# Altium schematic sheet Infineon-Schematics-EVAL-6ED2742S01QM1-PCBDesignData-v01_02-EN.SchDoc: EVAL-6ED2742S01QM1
size A3; ApprovedBy: IFCX; Author: Liang Guozhu; CompanyName: Infineon Technologies Xi’an Co., Ltd; Engineer: <Rel.>; Organization: IFCX IPC ISD SYS; Address1: IFCX IPC ISD SYS; Address2: 3rd Floor, No.16, District C, ChuangYe Park,; Address3: No.69 JinYe Road,High-tech Zone, Xi'an, Shaanxi,710077 P.R.C; Address4: China; DocumentNumber: 1; Revision: V1.1; SheetNumber: 1; SheetTotal: 1; Release: No; PageSetup: Record=PageOptions¦CenterHorizontal=True¦CenterVertical=True¦PrintScale=1.01¦XCorrection=1.00¦YCorrection=1.00¦PrintKind=0¦BorderSize=5000000¦LeftOffset=0¦BottomOffset=0¦Orientation=2¦PaperLength=1000¦PaperWidth=1000¦Scale=100¦PaperSource=7¦PrintQuality=-4¦MediaType=1¦DitherType=10¦PaperKind=A3¦PrintScaleMode=1; Doc_ConfidentialStatus: <Doc_ConfidentialStatus>; Doc_Preliminary: <Doc_Preliminary>
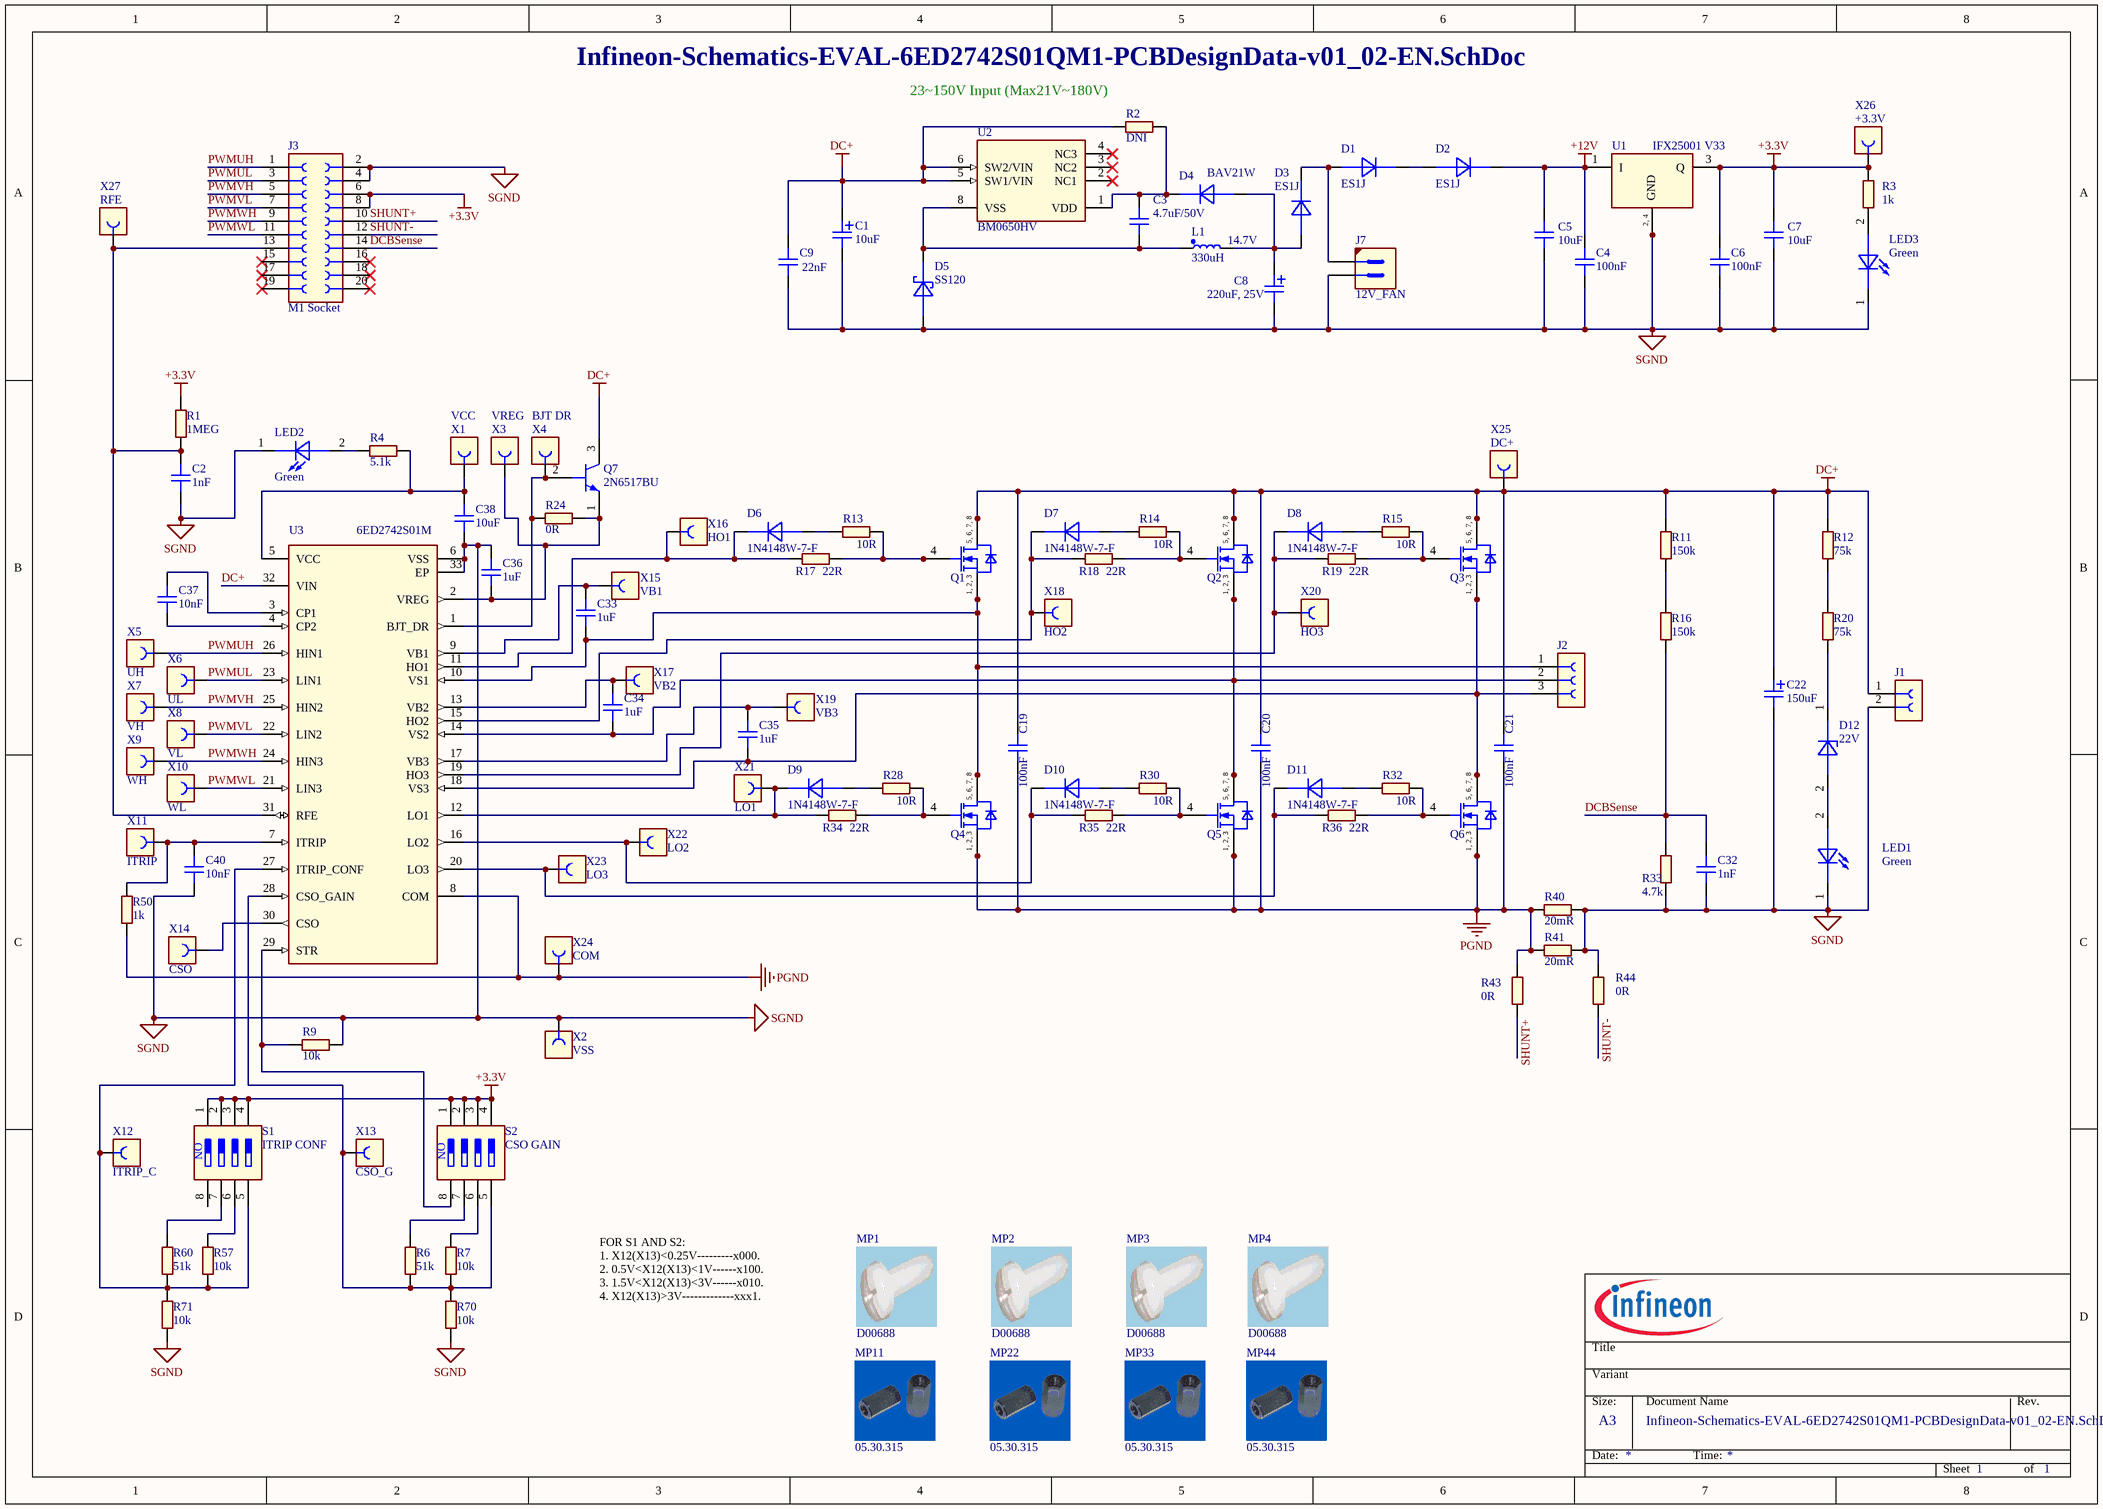
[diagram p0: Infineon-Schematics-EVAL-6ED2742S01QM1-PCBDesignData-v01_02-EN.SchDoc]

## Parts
C1  10uF  [CAPPRD500W60D1000H2150B]
C2  1nF  [CAPC1608X90N]
C3  4.7uF/50V  [CAPC2013X135N]
C4  100nF  [CAPC2013X94N]
C5  10uF  [CAPC1608X90N]
C6  100nF  [CAPC2013X94N]
C7  10uF  [CAPC1608X90N]
C8  220uF, 25V  [CAPPRD350W60D800H1300B]
C9  22nF  [CAPC2013X135N]
C19  100nF  [CAPC3216X180N-2]
C20  100nF  [CAPC3216X180N-2]
C21  100nF  [CAPC3216X180N-2]
C22  150uF  [CAPPRD750W80D1800H2650B]
C32  1nF  [CAPC2013X88N]
C33  1uF  [CAPC1608X90N]
C34  1uF  [CAPC1608X90N]
C35  1uF  [CAPC1608X90N]
C36  1uF  [CAPC1608X90N]
C37  10nF  [CAPC1608X90N]
C38  10uF  [CAPC2013X95N]
C40  10nF  [CAPC1608X90N]
D1  ES1J  [DIOM5027X244N-1]
D2  ES1J  [DIOM5027X244N-1]
D3  ES1J  [DIOM5027X244N-1]
D4  BAV21W  [SOD3715X145N]
D5  SS120  [DIOM5127X229N]
D6  1N4148W-7-F  [SOD3715X145N]
D7  1N4148W-7-F  [SOD3715X145N]
D8  1N4148W-7-F  [SOD3715X145N]
D9  1N4148W-7-F  [SOD3715X145N]
D10  1N4148W-7-F  [SOD3715X145N]
D11  1N4148W-7-F  [SOD3715X145N]
D12  22V  [DIOMELF3516N-1]
J1  691216510002S  [CON-TER-THT-691216510002S]  (value not drawn)
J2  691216510003S  [CON-TER-THT-691216510003S]  (value not drawn)
J3  M1 Socket  [CON-F-THT-613020243121]
J7  12V_FAN  [CON-M-THT-61300211121]
L1  330uH  [INDRD500W65D950H1350B]
LED1  Green  [LEDSC160X80X80-2N-1]
LED2  Green  [LEDSC160X80X80-2N-1]
LED3  Green  [LEDSC160X80X80-2N-1]
MP1  D00688  [SCREW_M3X10_D00688]
MP2  D00688  [SCREW_M3X10_D00688]
MP3  D00688  [SCREW_M3X10_D00688]
MP4  D00688  [SCREW_M3X10_D00688]
MP11  05.30.315  [HEX-STANDOFF_M3X15_0530315]
MP22  05.30.315  [HEX-STANDOFF_M3X15_0530315]
MP33  05.30.315  [HEX-STANDOFF_M3X15_0530315]
MP44  05.30.315  [HEX-STANDOFF_M3X15_0530315]
Q1  igfet_n_ch_enh_dio_1s2s3s4g5d6d7d8d_8p  [IFX-PG-TSON-8-3]  (value not drawn)
Q2  igfet_n_ch_enh_dio_1s2s3s4g5d6d7d8d_8p  [IFX-PG-TSON-8-3]  (value not drawn)
Q3  igfet_n_ch_enh_dio_1s2s3s4g5d6d7d8d_8p  [IFX-PG-TSON-8-3]  (value not drawn)
Q4  igfet_n_ch_enh_dio_1s2s3s4g5d6d7d8d_8p  [IFX-PG-TSON-8-3]  (value not drawn)
Q5  igfet_n_ch_enh_dio_1s2s3s4g5d6d7d8d_8p  [IFX-PG-TSON-8-3]  (value not drawn)
Q6  igfet_n_ch_enh_dio_1s2s3s4g5d6d7d8d_8p  [IFX-PG-TSON-8-3]  (value not drawn)
Q7  2N6517BU  [TO-92-THT-2N6517BU]
R1  1MEG  [RESC1609X50N]
R2  DNI  [RESC3216X60N]
R3  1k  [RESC2113X50N]
R4  5.1k  [RESC1609X50N]
R6  51k  [RESC1609X50N]
R7  10k  [RESC1608X55N-1]
R9  10k  [RESC1608X55N-1]
R11  150k  [RESC2113X50N]
R12  75k  [RESC2113X50N]
R13  10R  [RESC2113X50N]
R14  10R  [RESC2113X50N]
R15  10R  [RESC2113X50N]
R16  150k  [RESC2113X50N]
R17  22R  [RESC2113X50N]
R18  22R  [RESC2113X50N]
R19  22R  [RESC2113X50N]
R20  75k  [RESC2113X50N]
R24  0R  [RESC1608X55N-1]
R28  10R  [RESC2113X50N]
R30  10R  [RESC2113X50N]
R32  10R  [RESC2113X50N]
R33  4.7k  [RESC2013X60N-1]
R34  22R  [RESC2113X50N]
R35  22R  [RESC2113X50N]
R36  22R  [RESC2113X50N]
R40  20mR  [RESC6432X89N-1]
R41  20mR  [RESC6432X89N-1]
R43  0R  [RESC2113X50N]
R44  0R  [RESC2113X50N]
R50  1k  [RESC1608X55N-1]
R57  10k  [RESC1608X55N-1]
R60  51k  [RESC1609X50N]
R70  10k  [RESC1608X55N-1]
R71  10k  [RESC1608X55N-1]
S1  ITRIP CONF  [SW-DIP-SMD-A6H-4102]
S2  CSO GAIN  [SW-DIP-SMD-A6H-4102]
U1  IFX25001 V33  [SOT230P700X170-4N-1]
U2  BM0650HV  [SOIC127P600X175-7_8N]
U3  6ED2742S01M  [QFN50P500X500X90-33N-V]
X1  VCC  [TPCW140D210H530]
X2  VSS  [TPCW140D210H530]
X3  VREG  [TPCW140D210H530]
X4  BJT DR  [TPCW140D210H530]
X5  UH  [TPCW140D210H530]
X6  UL  [TPCW140D210H530]
X7  VH  [TPCW140D210H530]
X8  VL  [TPCW140D210H530]
X9  WH  [TPCW140D210H530]
X10  WL  [TPCW140D210H530]
X11  ITRIP  [TPCW140D210H530]
X12  ITRIP_C  [TPCW140D210H530]
X13  CSO_G  [TPCW140D210H530]
X14  CSO  [TPCW140D210H530]
X15  VB1  [TPCW140D210H530]
X16  HO1  [TPCW140D210H530]
X17  VB2  [TPCW140D210H530]
X18  HO2  [TPCW140D210H530]
X19  VB3  [TPCW140D210H530]
X20  HO3  [TPCW140D210H530]
X21  LO1  [TPCW140D210H530]
X22  LO2  [TPCW140D210H530]
X23  LO3  [TPCW140D210H530]
X24  COM  [TPCW140D210H530]
X25  DC+  [TPCW140D210H530]
X26  +3.3V  [TPCW140D210H530]
X27  RFE  [TPCW140D210H530]

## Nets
+3.3V: C6.2 C7.1 J3.6 J3.8 R1.2 R3.2 S1.1 S1.2 S1.3 S1.4 S2.1 S2.2 S2.3 S2.4 U1.3(Q) X26.1
+12V: C4.2 C5.1 D2.1(Cathode) U1.1(I)
DC+: C1.1 C9.2 C19.2 C20.2 C21.2 C22.1 J1.1 Q1.5(DRAIN) Q1.6(DRAIN) Q1.7(DRAIN) Q1.8(DRAIN) Q2.5(DRAIN) Q2.6(DRAIN) Q2.7(DRAIN) Q2.8(DRAIN) Q3.5(DRAIN) Q3.6(DRAIN) Q3.7(DRAIN) Q3.8(DRAIN) Q7.3(COLLECTOR) R2.1 R11.2 R12.2 U2.5(SW1/VIN) U2.6(SW2/VIN) U3.32(VIN) X25.1
PGND: C19.1 C20.1 C21.1 Q4.1(SOURCE) Q4.2(SOURCE) Q4.3(SOURCE) Q5.1(SOURCE) Q5.2(SOURCE) Q5.3(SOURCE) Q6.1(SOURCE) Q6.2(SOURCE) Q6.3(SOURCE) R40.1 R41.1 R43.1 R50.1 U3.8(COM) X24.1
SGND: C1.2 C2.1 C4.1 C5.2 C6.1 C7.2 C8.2 C9.1 C22.2 C32.1 C36.2 C38.2 C40.1 D5.2(Anode) J1.2 J3.2 J3.4 J7.2 LED1.1(Cathode) LED2.1(Cathode) LED3.1(Cathode) R9.2 R33.2 R40.2 R41.2 R44.2 R70.1 R71.1 U1.2(GND) U1.4(GND) U3.6(VSS) U3.33(EP) X2.1
DCBSense: C32.2 J3.14 R16.1 R33.1
PWMUH: J3.1 U3.26(HIN1) X5.1
PWMUL: J3.3 U3.23(LIN1) X6.1
PWMVH: J3.5 U3.25(HIN2) X7.1
PWMVL: J3.7 U3.22(LIN2) X8.1
PWMWH: J3.9 U3.24(HIN3) X9.1
PWMWL: J3.11 U3.21(LIN3) X10.1
SHUNT+: J3.10 R43.2
SHUNT-: J3.12 R44.1
NetC2_2: C2.2 J3.13 R1.1 U3.31(RFE) X27.1
NetC3_1: C3.1 D5.1(Cathode) L1.1 U2.8(VSS)
NetC3_2: C3.2 D4.1(Cathode) R2.2 U2.1(VDD)
NetC8_1: C8.1 D3.2(Anode) D4.2(Anode) L1.2
NetC33_1: C33.1 J2.1 Q1.1(SOURCE) Q1.2(SOURCE) Q1.3(SOURCE) Q4.5(DRAIN) Q4.6(DRAIN) Q4.7(DRAIN) Q4.8(DRAIN) U3.10(VS1)
NetC33_2: C33.2 U3.9(VB1) X15.1
NetC34_1: C34.1 J2.2 Q2.1(SOURCE) Q2.2(SOURCE) Q2.3(SOURCE) Q5.5(DRAIN) Q5.6(DRAIN) Q5.7(DRAIN) Q5.8(DRAIN) U3.14(VS2)
NetC34_2: C34.2 U3.13(VB2) X17.1
NetC35_1: C35.1 J2.3 Q3.1(SOURCE) Q3.2(SOURCE) Q3.3(SOURCE) Q6.5(DRAIN) Q6.6(DRAIN) Q6.7(DRAIN) Q6.8(DRAIN) U3.18(VS3)
NetC35_2: C35.2 U3.17(VB3) X19.1
NetC36_1: C36.1 Q7.1(EMITTER) R24.2 U3.2(VREG) X3.1
NetC37_1: C37.1 U3.4(CP2)
NetC37_2: C37.2 U3.3(CP1)
NetC38_1: C38.1 R4.2 U3.5(VCC) X1.1
NetC40_2: C40.2 R50.2 U3.7(ITRIP) X11.1
NetD1_1: D1.1(Cathode) D2.2(Anode)
NetD1_2: D1.2(Anode) D3.1(Cathode) J7.1
NetD6_1: D6.1(Cathode) R17.1 U3.11(HO1) X16.1
NetD6_2: D6.2(Anode) R13.1
NetD7_1: D7.1(Cathode) R18.1 U3.15(HO2) X18.1
NetD7_2: D7.2(Anode) R14.1
NetD8_1: D8.1(Cathode) R19.1 U3.19(HO3) X20.1
NetD8_2: D8.2(Anode) R15.1
NetD9_1: D9.1(Cathode) R34.1 U3.12(LO1) X21.1
NetD9_2: D9.2(Anode) R28.1
NetD10_1: D10.1(Cathode) R35.1 U3.16(LO2) X22.1
NetD10_2: D10.2(Anode) R30.1
NetD11_1: D11.1(Cathode) R36.1 U3.20(LO3) X23.1
NetD11_2: D11.2(Anode) R32.1
NetD12_1: D12.1(CATHODE) R20.1
NetD12_2: D12.2(ANODE) LED1.2(Anode)
NetLED2_2: LED2.2(Anode) R4.1
NetLED3_2: LED3.2(Anode) R3.1
NetQ1_4: Q1.4(GATE) R13.2 R17.2
NetQ2_4: Q2.4(GATE) R14.2 R18.2
NetQ3_4: Q3.4(GATE) R15.2 R19.2
NetQ4_4: Q4.4(GATE) R28.2 R34.2
NetQ5_4: Q5.4(GATE) R30.2 R35.2
NetQ6_4: Q6.4(GATE) R32.2 R36.2
NetQ7_2: Q7.2(BASE) R24.1 U3.1(BJT_DR) X4.1
NetR6_1: R6.1 R7.1 R70.2 S2.5 U3.28(CSO_GAIN) X13.1
NetR6_2: R6.2 S2.7
NetR7_2: R7.2 S2.6
NetR9_1: R9.1 S2.8 U3.29(STR)
NetR11_1: R11.1 R16.2
NetR12_1: R12.1 R20.2
NetR57_1: R57.1 R60.1 R71.2 S1.5 U3.27(ITRIP_CONF) X12.1
NetR57_2: R57.2 S1.6
NetR60_2: R60.2 S1.7
NetU3_30: U3.30(CSO) X14.1

Not connected (* = marked no-connect by the designer): J3 15* 16* 17* 18* 19* 20*; S1 8; U2 2(NC1)* 3(NC2)* 4(NC3)*

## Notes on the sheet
- (near R2) 23
  50V Input (Max21V
  80V)
- (near L1) 14.7V
- FOR S1 AND S2:
  1. X12(X13)<0.25V---------x000.
  2. 0.5V<X12(X13)<1V------x100.
  3. 1.5V<X12(X13)<3V------x010.
  4. X12(X13)>3V-------------xxx1.

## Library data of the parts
C1 = 641748: CAP / ELCO / 10uF / 200V / 20% / Aluminiumelectrolytic / -25¡ãC to 105¡ãC / 5.00mm C X 0.60mm W 10.00mm Dia X 21.50mm H / - / -; Multible Parts: No; Manufacturer: Wurth Elektronik; Manufacturer Order Number: 860241075003; Symbol Type: Capacitor; Single; Polarized; 2 Pins; Pin 1 Positive; Alternate View: Yes; Article Number: 641748; Version Number: V01; Combined Parameters: TC:Aluminiumelectrolytic;Tol.:-20%/+20%;Vdc:200V; QuickPick: 10uF / 200V / 20% / Aluminiumelectrolytic / Radial; Type: Polarized; Style: Single; ComponentStatus: Released; PLMStatus: Active
C2 = 272935: CAP / - / 1nF / 25V / 10% / X7R (EIA) / -55¡ãC to 125¡ãC / 0603(1608) / SMD / -; Multiple Parts: No; Legacy PartNumber: CAP01003594; Manufacturer: MuRata; Manufacturer Order Number: GRM188R71E102KA01; Symbol Type: Capacitor; Single; Standard; 2 Pins; Alternate View: Yes; Article Number: 272935; Version Number: V01; Combined Parameters: TC:X7R (EIA);Tol.:-10%/+10%;Vdc:25V; QuickPick: 1nF / 25V / 10% / X7R (EIA) / CAPC1608X90N; Type: Standard; Style: Single; Package Metric: 1608; Package Imperial: 0603; ComponentStatus: Released; PLMStatus: Obsolete
C3 = 278629: Chip Monolithic Ceramic Capacitor; Multiple Parts: No; Legacy PartNumber: CAP01004770; Manufacturer: MuRata; Manufacturer Order Number: GRM21BR61H475KE51; Symbol Type: Capacitor; Single; Standard; 2 Pins; Alternate View: Yes; Article Number: 278629; Version Number: V01; Value: 4.7uF; Tolerance Neg: 10%; Combined Parameters: TC:X5R (EIA);Tol.:-10%/+10%;Vdc:50V; QuickPick: 4.7uF / 50V / 10% / X5R (EIA) / CAPC2013X135N; Type: Standard; Style: Single; Package Metric: 2012; Package Imperial: 0805; ComponentStatus: Released; PLMStatus: Active; Voltage DC (max): 50V
C4 C6 = 254358: Surface Mount Ceramic Capacitor 0.1uF 25V X7R 10%; Multiple Parts: No; Manufacturer: AVX; Manufacturer Order Number: 08053C104K4Z2A; Symbol Type: Capacitor; Single; Standard; 2 Pins; Alternate View: Yes; Article Number: 254358; Version Number: V00; Combined Parameters: TC:X7R (EIA);Tol.:-10%/+10%;Vdc:25V; QuickPick: 100nF / 25V / 10% / X7R (EIA) / 0805 (2012); Type: Standard; Style: Single; Automotive Qualified: AEC Q200; PLMStatus: Active
C5 C7 = 271780: Chip Monolithic Ceramic Capacitor; Multiple Parts: No; Legacy PartNumber: CAP01003363; Manufacturer: MuRata; Manufacturer Order Number: GRM188R60J106ME84; Symbol Type: Capacitor; Single; Standard; 2 Pins; Alternate View: Yes; Article Number: 271780; Version Number: V01; Tolerance Neg: 20%; Combined Parameters: TC:X5R (EIA);Tol.:-20%/+20%;Vdc:6.3V; QuickPick: 10uF / 6.3V / 20% / X5R (EIA) / CAPC1608X90N; Type: Standard; Style: Single; Package Metric: 1608; Package Imperial: 0603; ComponentStatus: Released; PLMStatus: Active; Voltage DC (max): 6.30V
C8 = 636068: CAP / ELCO / 220uF / 25V / 20% / Aluminiumelectrolytic / -40¡ãC to 105¡ãC / 3.50mm C X 0.60mm W 8.00mm Dia X 13.00mm H / - / -; Multible Parts: No; Manufacturer: Wurth Elektronik; Manufacturer Order Number: 860020474012; Symbol Type: Capacitor; Single; Polarized; 2 Pins; Pin 1 Positive; Alternate View: Yes; Article Number: 636068; Version Number: V01; Combined Parameters: TC:Aluminiumelectrolytic;Tol.:-20%/+20%;Vdc:25V; QuickPick: 220uF / 25V / 20% / Aluminiumelectrolytic / Radial; Type: Polarized; Style: Single; ComponentStatus: Released; PLMStatus: Active
C9 = 279773: CAP / - / 22nF / 250V / 10% / X7R (EIA) / -55¡ãC to 125¡ãC / 0805(2012) / SMD / -; Multiple Parts: No; Legacy PartNumber: CAP01005000; Manufacturer: MuRata; Manufacturer Order Number: GRM21BR72E223KW03; Symbol Type: Capacitor; Single; Standard; 2 Pins; Alternate View: Yes; Article Number: 279773; Version Number: V01; Combined Parameters: TC:X7R (EIA);Tol.:-10%/+10%;Vdc:250V; QuickPick: 22nF / 250V / 10% / X7R (EIA) / CAPC2013X135N; Type: Standard; Style: Single; Package Metric: 2012; Package Imperial: 0805; ComponentStatus: Released; PLMStatus: Not Recommended For New Designs
C19-C21 = 610534: Ceramic Capacitor 0.1uF 250V X7R 10% SMD 1206; Multiple Parts: No; Manufacturer: Samsung; Manufacturer Order Number: CL31B104KEHSNNE; Symbol Type: Capacitor; Single; Standard; 2 Pins; Alternate View: Yes; Article Number: 610534; Version Number: V01; Combined Parameters: TC:X7R (EIA);Tol.:-10%/+10%;Vdc:250V; QuickPick: 100nF / 250V / 10% / X7R (EIA) / 1206; Type: Standard; Style: Single; ComponentStatus: Released; PLMStatus: Active
C22 = 641470: CAP / ELCO / 150uF / 200V / 20% / Aluminiumelectrolytic / -25¡ãC to 105¡ãC / 7.50mm C X 0.80mm W 18.00mm Dia X 26.50mm H / - / -; Multible Parts: No; Manufacturer: Wurth Elektronik; Manufacturer Order Number: 860241081008; Symbol Type: Capacitor; Single; Polarized; 2 Pins; Pin 1 Positive; Alternate View: Yes; Article Number: 641470; Version Number: V01; Combined Parameters: TC:Aluminiumelectrolytic;Tol.:-20%/+20%;Vdc:200V; QuickPick: 150uF / 200V / 20% / Aluminiumelectrolytic / Radial; Type: Polarized; Style: Single; ComponentStatus: Released; PLMStatus: Active
C32 = 251057: Surface Mount Multilayer Ceramic Chip Capacitor; Multiple Parts: No; Legacy PartNumber: CAP00004113; Manufacturer: Kemet; Manufacturer Order Number: C0805C102K5RACTU; Symbol Type: Capacitor; Single; Standard; 2 Pins; Alternate View: Yes; Article Number: 251057; Version Number: V01; Tolerance Neg: 10%; Combined Parameters: TC:X7R (EIA);Tol.:-10%/+10%;Vdc:50V; QuickPick: 1nF / 50V / 10% / X7R (EIA) / 0805; Type: Standard; Style: Single; Package Metric: 2012; Package Imperial: 0805; PLMStatus: Active; Voltage DC (max): 50V
C33-C36 = 272975: CAP / - / 1uF / 25V / 10% / X7R (EIA) / -55¡ãC to 125¡ãC / 0603(1608) / SMD / -; Multiple Parts: No; Legacy PartNumber: CAP01003602; Manufacturer: MuRata; Manufacturer Order Number: GRM188R71E105KA12; Symbol Type: Capacitor; Single; Standard; 2 Pins; Alternate View: Yes; Article Number: 272975; Version Number: V01; Combined Parameters: TC:X7R (EIA);Tol.:-10%/+10%;Vdc:25V; QuickPick: 1uF / 25V / 10% / X7R (EIA) / CAPC1608X90N; Type: Standard; Style: Single; Package Metric: 1608; Package Imperial: 0603; ComponentStatus: Released; PLMStatus: Active
C37 C40 = 272945: CAP / - / 10nF / 25V / 5% / X7R (EIA) / -55¡ãC to 125¡ãC / 0603(1608) / SMD / -; Multiple Parts: No; Legacy PartNumber: CAP01003596; Manufacturer: MuRata; Manufacturer Order Number: GRM188R71E103JA01; Symbol Type: Capacitor; Single; Standard; 2 Pins; Alternate View: Yes; Article Number: 272945; Version Number: V01; Combined Parameters: TC:X7R (EIA);Tol.:-5%/+5%;Vdc:25V; QuickPick: 10nF / 25V / 5% / X7R (EIA) / CAPC1608X90N; Type: Standard; Style: Single; Package Metric: 1608; Package Imperial: 0603; ComponentStatus: Released; PLMStatus: Not Recommended For New Designs
C38 = 277107: Chip Monolithic Ceramic Capacitor; Multiple Parts: No; Legacy PartNumber: CAP01004436; Manufacturer: MuRata; Manufacturer Order Number: GRM219R61E106KA12; Symbol Type: Capacitor; Single; Standard; 2 Pins; Alternate View: Yes; Article Number: 277107; Version Number: V01; Tolerance Neg: 10%; Combined Parameters: TC:X5R (EIA);Tol.:-10%/+10%;Vdc:25V; QuickPick: 10uF / 25V / 10% / X5R (EIA) / CAPC2013X95N; Type: Standard; Style: Single; Package Metric: 2012; Package Imperial: 0805; PLMStatus: Active; Voltage DC (max): 25V
D1-D3 = 394773: 1.0A Ultra Fast Recovery Rectifier; Legacy PartNumber: DIO01300264; Manufacturer: ON Semiconductor; Symbol Type: Standard Diode Symbol, 2 Leads, 1 Cathode, 2 Anode; Article Number: 394773; Version Number: V01; Combined Parameters: Vf:1.7V;If:1A;Ur:600V;Ir:5uA;Pmax:1.47W; QuickPick: Standard Diode / SMA (DO-214AC); Type: Standard Diode; Style: Single; Automotive Qualified: No; ComponentStatus: Released; PLMStatus: Active; Second Source allowed: Yes; Voltage DC (max): na
D4 = 394723: Surface Mount Fast Switching Diode; Legacy PartNumber: DIO01300257; Manufacturer: Diodes Incorporated; Manufacturer Order Number: BAV19W-7-F; Symbol Type: Standard Diode Symbol, 2 Leads, 1 Cathode, 2 Anode; Article Number: 394723; Version Number: V01; Value: BAV19W-7-F; Combined Parameters: Vf:1.5V;If:400mA;Ur:120V;Ir:100uA;Pmax:250mW; QuickPick: Standard Diode / SOD-123; Type: Standard Diode; Style: Single; Automotive Qualified: AEC Q101; ComponentStatus: Released; PLMStatus: Active; Second Source allowed: Yes; Voltage DC (max): na
D5 = 394491: Surface Mount Schottky Barrier Rectifier, 20V; Legacy PartNumber: DIO01300226; Manufacturer: Vishay; Manufacturer Order Number: SS12HE3_B/H; Symbol Type: Standard Schottky Diode Symbol, 1 Cathode, 2 Anode; Article Number: 394491; Version Number: V01; Value: SS12HE3_B/H; Combined Parameters: Vf:500mV;If:1A;Ur:20V;Ir:200uA;Pmax:-; QuickPick: Schottky Diode / DO-214AC (SMA); Type: Schottky Diode; Style: Single; Automotive Qualified: AEC Q101; PLMStatus: Active; Second Source allowed: Yes; Voltage DC (max): na
D6-D11 = 394268: Surface Mount Fast Switching Diode; Legacy PartNumber: DIO01300202; Manufacturer: Diodes Incorporated; Symbol Type: Standard Diode Symbol, 2 Leads, 1 Cathode, 2 Anode; Article Number: 394268; Version Number: V01; Combined Parameters: Vf:1.25V;If:300mA;Ur:100V;Ir:1uA;Pmax:400mW; QuickPick: Standard Diode / SOD123; Type: Standard Diode; Style: Single; Automotive Qualified: No; ComponentStatus: Released; PLMStatus: Active; Second Source allowed: Yes; Voltage DC (max): na
D12 = 394392: Zener Diode, 5% 22V; Legacy PartNumber: DIO01300216; Manufacturer: Solid State Devices Inc.; Manufacturer Order Number: SZ25B22SM; Symbol Type: Standard Zener Diode, 1 Cathode, 2 Anode; Article Number: 394392; Version Number: V01; Combined Parameters: Vf:-;If:-;Ur:17V;Ir:100nA;Pmax:-; QuickPick: Zener Diode / SMD; Style: Single; Automotive Qualified: No; ComponentStatus: Released; PLMStatus: Active; Second Source allowed: Yes; Voltage DC (max): na
J1 = 629821: Horizontal Cable Entry With Rising Cage Clamp - WR-TBL, 2 Pins; Manufacturer: Wurth Elektronik; Article Number: 629821; Version Number: V01; Legacy DeviceID: WE_691216510002S; Combined Parameters: Board-to-Cable Socket (female);2x1;Mounting:Onboard;Orient:0¡ã (vertical);Shielded:No; QuickPick: 0¡ã (vertical) / Board-to-Cable; Style: Terminal Block; Automotive Qualified: No; ComponentStatus: Released; PLMStatus: Active; Second Source allowed: Yes; Voltage DC (max): na
J2 = 618457: Horizontal Cable Entry With Rising Cage Clamp - WR-TBL, 3Pins; Manufacturer: Wurth Elektronik; Article Number: 618457; Version Number: V01; Legacy DeviceID: WE_691216510003S; Combined Parameters: Board-to-Cable Socket (female);3x1;Mounting:THT;Orient:0¡ã (vertical);Shielded:No; QuickPick: 0¡ã (vertical) / Board-to-Cable; Style: Terminal Block; Automotive Qualified: No; ComponentStatus: Released; PLMStatus: Active; Second Source allowed: Yes; Voltage DC (max): na
J3 = 618241: WR-PHD 2.54 mm Angled Dual Socket Header; Manufacturer: Wurth Elektronik; Manufacturer Order Number: 613020243121; Symbol type: Socket 10X2 pins; Article Number: 618241; Version Number: V01; Legacy DeviceID: WE_613020243121; Value: 613020243121; Combined Parameters: Board-to-Board Socket (female);10x2;Mounting:THT;Orient:90¡ã (right angle);Shielded:No; QuickPick: 90¡ã (right angle) / Board-to-Board; Automotive Qualified: No; ComponentStatus: Released; PLMStatus: Active; Second Source allowed: Yes; Voltage DC (max): na
J7 = 386760: Header, 2.54mm Pitch, 2 pin, Vertical, Single Row; Legacy PartNumber: CON01500943; Manufacturer: Wurth Elektronik; Manufacturer Order Number: 61300211121; Article Number: 386760; Version Number: V01; Legacy DeviceID: WE_61300211121; Value: 61300211121; Combined Parameters: Board-to-Board Header (male);2x1;Mounting:THT;Orient:0Â° (vertical);Shielded:No; QuickPick: 0Â° (vertical) / Board-to-Board; Style: Strip; Automotive Qualified: No; PLMStatus: Active; Second Source allowed: Yes; Voltage DC (max): na
L1 = 641478: IND / STD / 330uH / 1.1A / 10% / -40¡ãC to 125¡ãC / 470mR / Radial / Inductor,Radial;5.00mm C X 0.65mm W 9.50mm Dia X 13.50mm H / - / -; Multiple Parts: No; Manufacturer: Wurth Elektronik; Manufacturer Order Number: 7447452331; Symbol Type: Inductor; Single; Standard; Polarized; 2 Pins; Alternate View: Yes; Article Number: 641478; Version Number: V01; Combined Parameters: Tol.:-10%/+10%;Rdc:470mR;Idc:1.1A;Fres:2.4MHz; QuickPick: 330uH / Standard / Radial; Type: Standard; Style: Single; ComponentStatus: Released; PLMStatus: Active; Voltage DC (max): na
LED1-LED3 = 625451: WL-SMCW SMT Mono-color Chip LED Waterclear, Green, 515nm; Manufacturer: Wurth Elektronik; Manufacturer Order Number: 150060GS75000; Symbol Type: Standard LED Symbol, 1 Cathode, 2 Anode; Article Number: 625451; Version Number: V01; Combined Parameters: Vf:3.5V;If:30mA;Ur:5V;Ir:10uA;Pmax:105mW; QuickPick: LED / 1608 (0603); Style: Single; Automotive Qualified: No; ComponentStatus: Released; PLMStatus: Active; Second Source allowed: Yes; Voltage DC (max): na
MP1-MP4 = 416878: M3 X 10mm Pan Head,Cross Head Metric Screw, 5.6mm X 2.4mm Head, Nylon 6,6; Legacy PartNumber: MEC10000028; Manufacturer: Duratool; Symbol Type: Pan,Cross Head Metric Screw , M3/M4/M5/M6 types; Article Number: 416878; Version Number: V01; Legacy DeviceID: MEC_D00688; Combined Parameters: - - -x- -; Automotive Qualified: No; ComponentStatus: Released; PLMStatus: Active; Second Source allowed: Yes; Voltage DC (max): na
MP11 MP22 MP33 MP44 = 416846: Hex-Standoff / Female - Female M3 / 6 x 15 (DxH); Legacy PartNumber: MEC10000026; Manufacturer: ETTINGER; Article Number: 416846; Version Number: V01; Legacy DeviceID: MEC_05.30.315; Combined Parameters: - - -x- -; Automotive Qualified: No; ComponentStatus: Released; PLMStatus: Active; Second Source allowed: Yes; Voltage DC (max): na
Q1-Q6 = 612956: OptiMOS 5 Power-Transistor, 150 V, N-channel; Manufacturer: Infineon Technologies; Manufacturer Order Number: BSC074N15NS5; Symbol Type: Insulated-Gate Field-Effect Transistor (IGFET), N-Channel, Enhancement, Body Diode, Pin 1 Source, 2 Source, 3 Source, 4 Gate, 5 Drain, 6 Drain, 7 Drain, 8 Drain, 8 Pins; Article Number: 612956; Version Number: V01; Legacy DeviceID: IFX_BSC074N15NS5; Value: BSC074N15NS5; Combined Parameters: N-Channel Enhancement;Uds:150V;Id:114A;Rds:7.4R;P:214W; QuickPick: N-Channel Enhancement / 214W / 114A / 150V / PG-TSON-8-3; Type: N-Channel Enhancement; Style: Single; Automotive Qualified: No; ComponentStatus: Released; PLMStatus: Active; Second Source allowed: Yes; Voltage DC (max): na
Q7 = 614023: NPN Epitaxial Silicon Transistor, High Voltage Transistor; Manufacturer: ON Semiconductor; Symbol Type: NPN Bipolar Junction Transistor (BJT), Pin 1 Emitter, 2 Base, 3 Collector, 3 Pins; Article Number: 614023; Version Number: V01; Legacy DeviceID: ONSEMI_2N6517BU; Combined Parameters: NPN;Uce:350V;Ic:500mA;P:625mW;F:-; QuickPick: NPN / 625mW / 500mA / 350V / TO-92 (CASE 135AN); Style: Single; Automotive Qualified: No; ComponentStatus: Released; PLMStatus: Active; Second Source allowed: Yes; Voltage DC (max): na
R1 = 347312: RES / STD / 1MEG / 100mW / 1% / 100ppm/K / -55¡ãC to 155¡ãC / 0603 / SMD / -; Multiple Parts: No; Legacy PartNumber: RES01801485; Manufacturer: Vishay; Manufacturer Order Number: CRCW06031M00FK; Symbol Type: Resistor; Single; Standard; 2 Pins; Alternate View: Yes; Article Number: 347312; Version Number: V01; Combined Parameters: TCR:100ppm/K;Tol.:-1%/+1%;Vdc:75V;Idc:-;P:100mW; QuickPick: 1MEG / 1% / 0.1 / 0603; Style: Single; Automotive Qualified: AEC Q200; ComponentStatus: Released; PLMStatus: Active; Voltage DC (max): 75V
R2 = 351892: Standard Thick Film Chip Resistor; Multiple Parts: No; Legacy PartNumber: RES01802400; Manufacturer: Vishay; Manufacturer Order Number: CRCW12060000Z0; Symbol Type: Resistor; Single; Standard; 2 Pins; Alternate View: Yes; Article Number: 351892; Version Number: V01; Value: 0R; Combined Parameters: TCR:-;Tol.:-0R/+0R;Vdc:200V;Idc:3.5A;P:-; QuickPick: 0R / 0R / 1206; Style: Single; Automotive Qualified: AEC Q200; ComponentStatus: Released; PLMStatus: Active; Voltage DC (max): 200V
R3 = 349607: Standard Thick Film Chip Resistor; Multiple Parts: No; Legacy PartNumber: RES01801943; Manufacturer: Vishay; Manufacturer Order Number: CRCW08051K00FK; Symbol Type: Resistor; Single; Standard; 2 Pins; Alternate View: Yes; Article Number: 349607; Version Number: V01; Tolerance Neg: 1%; Combined Parameters: TCR:100ppm/K;Tol.:-1%/+1%;Vdc:150V;Idc:-;P:125mW; QuickPick: 1k / 1% / 0.1250 / 0805; Style: Single; Automotive Qualified: AEC Q200; PLMStatus: Active; Voltage DC (max): 150V
R4 = 346002: RES / STD / 5.1k / 100mW / 1% / 100ppm/K / -55¡ãC to 155¡ãC / 0603 / SMD / -; Multiple Parts: No; Legacy PartNumber: RES01801223; Manufacturer: Vishay; Manufacturer Order Number: CRCW06035K10FK; Symbol Type: Resistor; Single; Standard; 2 Pins; Alternate View: Yes; Article Number: 346002; Version Number: V01; Combined Parameters: TCR:100ppm/K;Tol.:-1%/+1%;Vdc:75V;Idc:-;P:100mW; QuickPick: 5.1k / 1% / 0.1 / 0603; Style: Single; Automotive Qualified: AEC Q200; ComponentStatus: Released; PLMStatus: Active; Voltage DC (max): 75V
R6 R60 = 346572: RES / STD / 51k / 100mW / 1% / 100ppm/K / -55¡ãC to 155¡ãC / 0603 / SMD / -; Multiple Parts: No; Legacy PartNumber: RES01801337; Manufacturer: Vishay; Manufacturer Order Number: CRCW060351K0FK; Symbol Type: Resistor; Single; Standard; 2 Pins; Alternate View: Yes; Article Number: 346572; Version Number: V01; Combined Parameters: TCR:100ppm/K;Tol.:-1%/+1%;Vdc:75V;Idc:-;P:100mW; QuickPick: 51k / 1% / 0.1 / 0603; Style: Single; Automotive Qualified: AEC Q200; ComponentStatus: Released; PLMStatus: Active; Voltage DC (max): 75V
R7 R9 R57 R70 R71 = 327886: RES / STD / 10k / 100mW / 1% / 100ppm/K / -55¡ãC to 155¡ãC / 0603 / SMD / -; Multiple Parts: No; Legacy PartNumber: RES00000101; Manufacturer: Yageo; Manufacturer Order Number: RC0603FR-0710KL; Symbol Type: Resistor; Single; Standard; 2 Pins; Alternate View: Yes; Article Number: 327886; Version Number: V01; Combined Parameters: TCR:100ppm/K;Tol.:-1%/+1%;Vdc:75V;Idc:-;P:100mW; QuickPick: 10k / 1% / 0.1 / 0603; Style: Single; ComponentStatus: Released; PLMStatus: Active; Voltage DC (max): 75V
R11 R16 = 350837: Standard Thick Film Chip Resistor; Multiple Parts: No; Legacy PartNumber: RES01802189; Manufacturer: Vishay; Manufacturer Order Number: CRCW0805150KFK; Symbol Type: Resistor; Single; Standard; 2 Pins; Alternate View: Yes; Article Number: 350837; Version Number: V01; Tolerance Neg: 1%; Combined Parameters: TCR:100ppm/K;Tol.:-1%/+1%;Vdc:150V;Idc:-;P:125mW; QuickPick: 150k / 1% / 0.1250 / 0805; Style: Single; Automotive Qualified: AEC Q200; ComponentStatus: Released; PLMStatus: Active; Voltage DC (max): 150V
R12 R20 = 350677: Standard Thick Film Chip Resistor; Multiple Parts: No; Legacy PartNumber: RES01802157; Manufacturer: Vishay; Manufacturer Order Number: CRCW080575K0FK; Symbol Type: Resistor; Single; Standard; 2 Pins; Alternate View: Yes; Article Number: 350677; Version Number: V01; Tolerance Neg: 1%; Combined Parameters: TCR:100ppm/K;Tol.:-1%/+1%;Vdc:150V;Idc:-;P:125mW; QuickPick: 75k / 1% / 0.1250 / 0805; Style: Single; Automotive Qualified: AEC Q200; ComponentStatus: Released; PLMStatus: Active; Voltage DC (max): 150V
R13-R15 R28 R30 R32 = 348467: Standard Thick Film Chip Resistor; Multiple Parts: No; Legacy PartNumber: RES01801715; Manufacturer: Vishay; Manufacturer Order Number: CRCW080510R0FK; Symbol Type: Resistor; Single; Standard; 2 Pins; Alternate View: Yes; Article Number: 348467; Version Number: V01; Tolerance Neg: 1%; Combined Parameters: TCR:100ppm/K;Tol.:-1%/+1%;Vdc:150V;Idc:-;P:125mW; QuickPick: 10R / 1% / 0.1250 / 0805; Style: Single; Automotive Qualified: AEC Q200; PLMStatus: Active; Voltage DC (max): 150V
R17-R19 R34-R36 = 348647: Standard Thick Film Chip Resistor; Multiple Parts: No; Legacy PartNumber: RES01801751; Manufacturer: Vishay; Manufacturer Order Number: CRCW080522R0FK; Symbol Type: Resistor; Single; Standard; 2 Pins; Alternate View: Yes; Article Number: 348647; Version Number: V01; Tolerance Neg: 1%; Combined Parameters: TCR:100ppm/K;Tol.:-1%/+1%;Vdc:150V;Idc:-;P:125mW; QuickPick: 22R / 1% / 0.1250 / 0805; Style: Single; Automotive Qualified: AEC Q200; PLMStatus: Active; Voltage DC (max): 150V
R24 = 328011: RES / STD / 0R / 100mW / 0R / 0ppm/K / -55¡ãC to 155¡ãC / 0603 / SMD / -; Multiple Parts: No; Legacy PartNumber: RES00000126; Manufacturer: Yageo; Manufacturer Order Number: RC0603JR-070RL; Symbol Type: Resistor; Single; Standard; 2 Pins; Alternate View: Yes; Article Number: 328011; Version Number: V01; Combined Parameters: TCR:0ppm/K;Tol.:-0R/+0R;Vdc:75V;Idc:1A;P:100mW; QuickPick: 0R / 0R / 0.1 / 0603; Style: Single; ComponentStatus: Released; PLMStatus: Active; Voltage DC (max): 75V
R33 = 369410: 4.7k/150V/1%; Multiple Parts: No; Legacy PartNumber: RES01805818; Manufacturer: Bourns; Manufacturer Order Number: CR0805-FX-4701GLF; Symbol Type: Resistor; Single; Standard; 2 Pins; Alternate View: Yes; Article Number: 369410; Version Number: V01; Tolerance Neg: 1%; Combined Parameters: TCR:100ppm/K;Tol.:-1%/+1%;Vdc:150V;Idc:-;P:125mW; QuickPick: 4.7k / 1% / 0.1250 / 0805; PLMStatus: Active; Voltage DC (max): 150V
R40 R41 = 368506: Low Value Power Metal Strip Resistor; Multiple Parts: No; Legacy PartNumber: RES01805692; Manufacturer: Vishay; Manufacturer Order Number: WSL2512R0200FEA; Symbol Type: Resistor; Single; Standard; 2 Pins; Alternate View: Yes; Article Number: 368506; Version Number: V01; Tolerance Neg: 1%; Combined Parameters: TCR:75ppm/K;Tol.:-1%/+1%;Vdc:-;Idc:-;P:1W; QuickPick: 20mR / 1% / 1 / 2512; Style: Single; Automotive Qualified: AEC Q200; ComponentStatus: Released; PLMStatus: Active
R43 R44 = 347887: Standard Thick Film Chip Resistor; Multiple Parts: No; Legacy PartNumber: RES01801600; Manufacturer: Vishay; Manufacturer Order Number: CRCW08050000Z0; Symbol Type: Resistor; Single; Standard; 2 Pins; Alternate View: Yes; Article Number: 347887; Version Number: V01; Combined Parameters: TCR:-;Tol.:-0R/+0R;Vdc:150V;Idc:2.5A;P:-; QuickPick: 0R / 0R / 0805; Style: Single; Automotive Qualified: AEC Q200; PLMStatus: Active; Voltage DC (max): 150V
R50 = 327826: RES / STD / 1k / 100mW / 1% / 100ppm/K / -55¡ãC to 155¡ãC / 0603 / SMD / -; Multiple Parts: No; Legacy PartNumber: RES00000089; Manufacturer: Yageo; Manufacturer Order Number: RC0603FR-071KL; Symbol Type: Resistor; Single; Standard; 2 Pins; Alternate View: Yes; Article Number: 327826; Version Number: V01; Combined Parameters: TCR:100ppm/K;Tol.:-1%/+1%;Vdc:75V;Idc:-;P:100mW; QuickPick: 1k / 1% / 0.1 / 0603; Style: Single; ComponentStatus: Released; PLMStatus: Active; Voltage DC (max): 75V
S1 S2 = 474251: Slide DIP Switch with seal tape; Multiple Parts: No; Manufacturer: Omron; Manufacturer Order Number: A6H-4102-P; Symbol Type: DIP-Switch 4 Positions; Article Number: 474251; Version Number: V01; Legacy DeviceID: OM_A6H-4102-P; Value: A6H-4102-P; ComponentStatus: Released; PLMStatus: Active; Second Source allowed: Yes; Voltage DC (max): na
U1 = 423357: Low Dropout Voltage Regulator, 3.3V Output; Legacy PartNumber: IFX01400494; Manufacturer: Infineon Technologies; Manufacturer Order Number: IFX25001ME V33; Article Number: 423357; Version Number: V01; Legacy DeviceID: IFX_IFX25001ME V33; Value: IFX25001ME V33; Combined Parameters: Linear Not applicable -;Vo:3.30V to 3.30V; QuickPick: Linear / PG-SOT223-4; Style: Not applicable; Automotive Qualified: No; ComponentStatus: Released; PLMStatus: Active; Second Source allowed: Yes; Voltage DC (max): na
U2 = 613742: PFM Controller and 200V Smart power with high avalanche capability MOSFET; Multiple Parts: No; Manufacturer: Bookly; Symbol type: 200V High-Voltage DC-DC Buck Converter; Article Number: 613742; Version Number: V01; Legacy DeviceID: BK_BM0650HV; Combined Parameters: Switched DC/DC -;Vo:- to 14.7V; QuickPick: Switched / SOP-8; Style: DC/DC; ComponentStatus: Released; PLMStatus: Active; Second Source allowed: Yes; Voltage DC (max): na
U3 = 612085: 160 V pre-regulated three phase SOI gate driver; Manufacturer: Infineon Technologies; Symbol Type: 160 V pre-regulated three phase SOI gate driver with integrated charge pump; Alternate View: No; Product Name: IFX_6ED2742S01M; Pins Electrical: 33; Temperature (min.) [°C]: -40; Temperature (max.) [°C]: 125; Component Height (max.)  [mm]: 0.9; Digital Supply Voltage (min.) [V]: 6; Digital Supply Voltage (max.) [V]: 140; Output Current (max.): 1A; ComponentStatus: Created; Description (long): The 160 V SOI based gate driver designed for three phase BLDC motor drive applications Integrated bootstrap diodes are used to supply the three external high sides charging bootstrap capacitors and supports 100% duty cycle operation by a trickle charge pump; PLM Status: Preliminary; Article Number: 612085; Version Number: V01; Combined Parameters: Industrial Driver;Vdc min/max:6V/140V;Iout:1A;Fmax:-; QuickPick: PG-VQFN-32-13; PLMStatus: Active; Second Source allowed: Yes; Voltage DC (max): na
X1-X27 = 377299: Black Bead Terminal, Assembly 1.32 mm hole; Multiple Parts: No; Legacy PartNumber: CON01500038; Manufacturer: Vero Technologies; Manufacturer Order Number: 20-2136; Symbol Type: Connector, 1 Lead, Female; Alternate View: Yes; Article Number: 377299; Version Number: V01; Legacy DeviceID: VER_20-2136; Value: 20-2136; Combined Parameters: Board-to-Cable None (onboard);1x1;Mounting:THT;Orient:None (onboard);Shielded:No; QuickPick: None (onboard) / Board-to-Cable; Style: Looped Terminal; ComponentStatus: Released; PLMStatus: Active; Voltage DC (max): na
